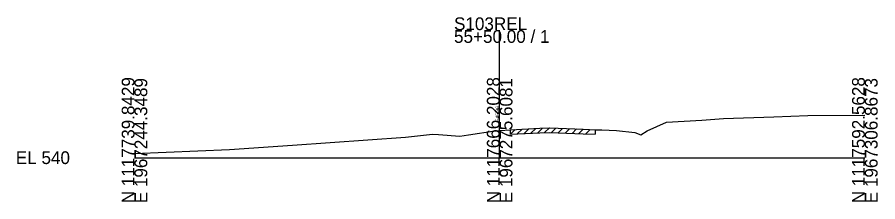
# Model space of a CAD drawing. Extents: x -26 to 163, y -10 to 24518.
# Drawn here: x -25.7 to 162.8, y 5990.3 to 6030.9 of the extents above; entities that cross this region are included whole.
import ezdxf

# ---------------------------------------------------------------- set-up
doc = ezdxf.new("R2010")
doc.units = 0
for name, color, linetype in [('RD_GPK_XS_Cell', 7, 'Continuous'), ('RD_XS_ExGround', 7, 'Continuous'), ('RD_XS_ExPaveRet', 7, 'Continuous'), ('RD_XS_TX_Elev_EX', 7, 'Continuous')]:
    doc.layers.add(name, color=color, linetype=linetype)

msp = doc.modelspace()

# ---------------------------------------------------------------- linework, layer by layer
at = {"layer": 'RD_GPK_XS_Cell'}
for p, q in [((80, 6000), (80, 6028.01)), ((0, 6000), (80, 6000)), ((80, 6000), (160, 6000))]:
    msp.add_line(p, q, dxfattribs=at)
at = {"layer": 'RD_XS_ExGround'}
msp.add_lwpolyline([(0, 6000.92), (20.84, 6001.79), (34.59, 6002.74), (59.35, 6004.5), (65.31, 6005.18), (66.61, 6005.09), (71.3, 6004.7), (73.18, 6005.01), (78.97, 6005.87), (80, 6005.96), (82.35, 6006.15), (88.82, 6006.47), (90.99, 6006.56), (98.33, 6006.23), (100.9, 6006.15), (102.39, 6006.12), (105.57, 6005.98), (109.58, 6005.54), (110.9, 6004.99), (112.34, 6005.88), (116.53, 6007.79), (124.32, 6008.26), (129.07, 6008.58), (140.06, 6008.98), (147.53, 6009.25), (160, 6009.34)], dxfattribs=at)
at = {"layer": 'RD_XS_ExPaveRet'}
for p, q in [((82.35, 6005.15), (83.4, 6006.2)), ((82.35, 6005.15), (82.35, 6006.15)), ((82.35, 6005.15), (88.82, 6005.47)), ((83.85, 6005.23), (84.9, 6006.28)), ((85.35, 6005.3), (86.4, 6006.35)), ((86.85, 6005.37), (87.9, 6006.42)), ((88.35, 6005.44), (89.39, 6006.49)), ((88.82, 6005.47), (90.99, 6005.56)), ((89.85, 6005.51), (90.89, 6006.56)), ((90.99, 6005.56), (98.33, 6005.23)), ((91.35, 6005.55), (92.3, 6006.5)), ((92.85, 6005.48), (93.8, 6006.44)), ((94.35, 6005.41), (95.3, 6006.37)), ((95.85, 6005.34), (96.8, 6006.3)), ((97.35, 6005.28), (98.3, 6006.23)), ((98.33, 6005.23), (100.9, 6005.15)), ((98.85, 6005.22), (99.81, 6006.18)), ((100.9, 6006.15), (100.9, 6005.15))]:
    msp.add_line(p, q, dxfattribs=at)

# ---------------------------------------------------------------- texts
at = {"layer": 'RD_GPK_XS_Cell'}
for s, p in [('S103REL', (70, 6028.01)), ('55+50.00 / 1', (70, 6025.21)), ('EL 540', (-26, 5998.6))]:
    msp.add_text(s, height=2.8, dxfattribs=at).set_placement(p)
for s, p in [('N 1117739.8429', (0, 5990)), ('E 1967244.3489', (2.8, 5990)), ('N 1117666.2028', (80, 5990)), ('E 1967275.6081', (82.8, 5990)), ('N 1117592.5628', (160, 5990)), ('E 1967306.8673', (162.8, 5990))]:
    msp.add_text(s, height=2.8, rotation=90, dxfattribs=at).set_placement(p)
at = {"layer": 'RD_XS_TX_Elev_EX'}
msp.add_text('545.96', height=0.8, rotation=90, dxfattribs=at).set_placement((79.9, 6007.96))

doc.saveas('drawing.dxf')
